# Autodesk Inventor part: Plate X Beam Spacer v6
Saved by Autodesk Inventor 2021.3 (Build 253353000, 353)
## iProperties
Created: 2022-12
Part Number: Plate X Beam Spacer v6
Material: Generic
Document SubType Name: Modeling
Designer: Administrator
Density: 1 g/cm^3
Appearance: Default
Title: Plate X Beam Spacer v6
Author: Administrator
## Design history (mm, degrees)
feature "Body1"
body "Solid1"
